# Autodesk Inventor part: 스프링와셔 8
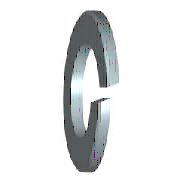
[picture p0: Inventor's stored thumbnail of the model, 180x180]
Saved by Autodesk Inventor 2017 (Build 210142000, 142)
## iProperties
IsCustomPart: 1
Created: 2012-02
Part Number: 스프링와셔 8
Material: 강철, 연강
Description: 스프링 잠금 와셔
Document SubType Name: Modeling
Standard: KS B 1324
Designer: mduedu
Standards Organization: KS
Language: ko-KR
Size Designation: 번호 3 - 8
Categories: <MemberInstance><Categories><Category DisplayName="조임쇠" InternalName="e4da775c-781d-43d5-af7c-5136215cf5a6" Mnemonic="FSTN"><Category DisplayName="와셔" InternalN
Density: 1 g/cm^3
Appearance: 파란색 - 벽 페인트 - 광택
Author: mduedu
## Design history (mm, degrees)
sketch "스케치1"
  geometry: C1 r 7.4 at (0, 0); C2 r 4.1 at (0, 0); 1 further point
  constraints: 2 centre point, 2 coincident
  dimensions: "d0" = 8.2 diameter of C2 (= SD1); "d1" = 14.8 diameter of C1 (= SD2)
extrude "본체" new body sketch "스케치1" distance "d2" = 2.5 (= SD); taper "d3" = 0 deg
sketch "스케치2"
  geometry: L1 (0, -4.1)-(0, 4.1) reference; L2 (2.5, 7.4)-(2.5, -7.4) reference; L3 (-1.2, 0)-(7.2, 0) reference; L4 (0, -0.5)-(2.5, 0.41); L5 (0, 0.5)-(2.5, 1.41)
  constraints: 4 end point, 4 point on line, 1 parallel
  dimensions: "d4" = 0.5 distance from line of L3 L4.start (= 0.2 x SD); "d5" = 0.5 distance from line of L3 L5.start (= 0.2 x SD); "d6" = 70 deg angle of L2 L4 (= FAWI)
extrude "절단부" cut sketch "스케치2" stored distance "d7" = 2.5 (= SD); taper "d8" = 0 deg
workaxis "Work Axis1"
workplane "Work Plane1"
body "Solid1"
other parameters: "SD1" = 8.2 [user parameter; used in 1 equation term], "SD2" = 14.8 [user parameter; used in 1 equation term], "SD" = 2.5 [user parameter; used in 4 equation terms], "FAWI" = 70 deg [user parameter; used in 1 equation term], "d9" = 0, "d10" = 0, "d11" = 0, "d12" = 0, "SDI" = 3.3 [user parameter], "NND" = 8 [user parameter]
